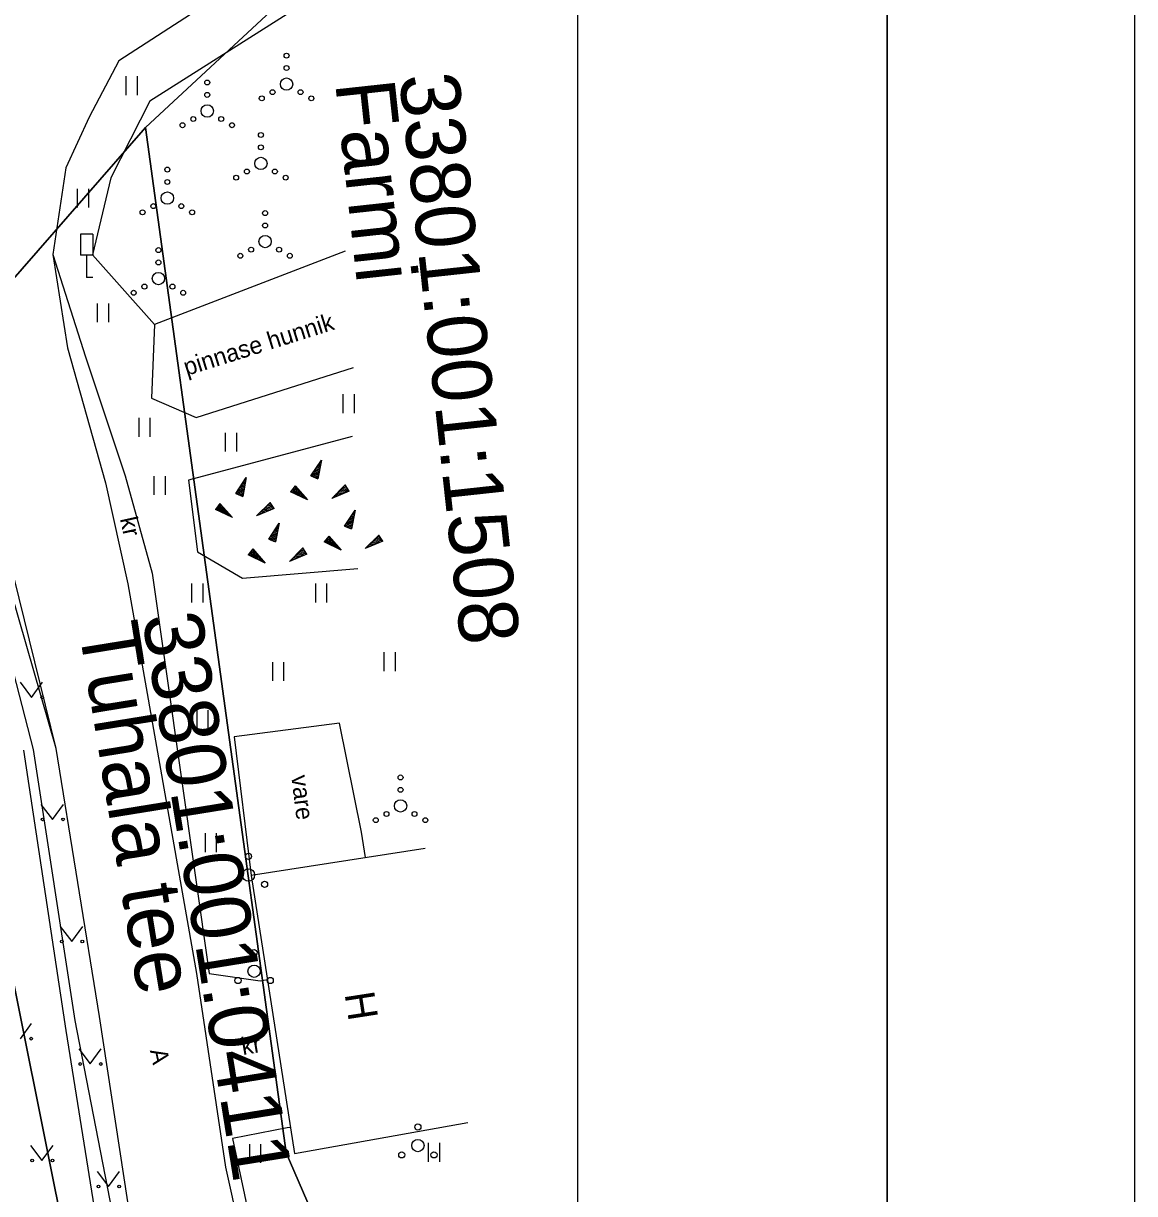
# Model space of a CAD drawing. Extents: x 554947 to 555436, y 6564938 to 6565792.
# Drawn here: x 555348.19 to 555393.07, y 6565480.81 to 6565528.08 of the extents above; entities that cross this region are included whole.
import ezdxf

# ---------------------------------------------------------------- set-up
doc = ezdxf.new("R2010")
doc.units = 0
for name, color, linetype in [('AED', 7, 'Continuous'), ('HALJASTUS', 7, 'Continuous'), ('HOONE', 7, 'Continuous'), ('LIIKLUS', 7, 'Continuous'), ('PIIR', 7, 'Continuous'), ('PR_SIDE', 7, 'Continuous'), ('PUU', 7, 'Continuous'), ('RELJEEF', 7, 'Continuous'), ('TEE', 7, 'Continuous'), ('VORMISTUS_3', 7, 'Continuous')]:
    doc.layers.add(name, color=color, linetype=linetype)

msp = doc.modelspace()

# ---------------------------------------------------------------- linework, layer by layer
at = {"layer": 'AED'}
msp.add_lwpolyline([(555353.187, 6565471.073), (555351.365, 6565478.297), (555349.912, 6565487.399), (555348.203, 6565498.717)], dxfattribs=at)
at = {"layer": 'HALJASTUS'}
for p, q in [((555352.324, 6565525.945), (555352.324, 6565525.183)), ((555352.779, 6565525.945), (555352.779, 6565525.183)), ((555350.36, 6565521.402), (555350.36, 6565520.641)), ((555350.815, 6565521.402), (555350.815, 6565520.641)), ((555351.166, 6565516.766), (555351.166, 6565516.005)), ((555351.621, 6565516.766), (555351.621, 6565516.005)), ((555361.091, 6565513.097), (555361.091, 6565512.335)), ((555361.546, 6565513.097), (555361.546, 6565512.335)), ((555352.843, 6565512.14), (555352.843, 6565511.379)), ((555353.298, 6565512.14), (555353.298, 6565511.379)), ((555356.338, 6565511.545), (555356.338, 6565510.783)), ((555356.793, 6565511.545), (555356.793, 6565510.783)), ((555353.46, 6565509.792), (555353.46, 6565509.031)), ((555353.915, 6565509.792), (555353.915, 6565509.031)), ((555354.98, 6565505.45), (555354.98, 6565504.689)), ((555355.435, 6565505.45), (555355.435, 6565504.689)), ((555359.98, 6565505.45), (555359.98, 6565504.689)), ((555360.435, 6565505.45), (555360.435, 6565504.689)), ((555362.751, 6565502.676), (555362.751, 6565501.915)), ((555363.206, 6565502.676), (555363.206, 6565501.915)), ((555358.242, 6565502.281), (555358.242, 6565501.52)), ((555358.697, 6565502.281), (555358.697, 6565501.52)), ((555348.055, 6565501.461), (555348.518, 6565500.854)), ((555348.518, 6565500.854), (555348.964, 6565501.461)), ((555355.188, 6565500.335), (555355.188, 6565499.574)), ((555355.643, 6565500.335), (555355.643, 6565499.574)), ((555348.895, 6565496.532), (555349.359, 6565495.925)), ((555349.359, 6565495.925), (555349.804, 6565496.532)), ((555355.523, 6565495.364), (555355.523, 6565494.603)), ((555355.978, 6565495.364), (555355.978, 6565494.603)), ((555349.676, 6565491.594), (555350.14, 6565490.987)), ((555350.14, 6565490.987), (555350.585, 6565491.594)), ((555348.068, 6565487.065), (555348.514, 6565487.672)), ((555350.42, 6565486.649), (555350.883, 6565486.043)), ((555350.883, 6565486.043), (555351.329, 6565486.649)), ((555348.474, 6565482.748), (555348.938, 6565482.141)), ((555348.938, 6565482.141), (555349.383, 6565482.748)), ((555357.313, 6565482.807), (555357.313, 6565482.046)), ((555357.768, 6565482.807), (555357.768, 6565482.046)), ((555364.538, 6565482.859), (555364.538, 6565482.097)), ((555364.993, 6565482.859), (555364.993, 6565482.097)), ((555351.163, 6565481.705), (555351.627, 6565481.098)), ((555351.627, 6565481.098), (555352.072, 6565481.705))]:
    msp.add_line(p, q, dxfattribs=at)
for points in [[(555361.377, 6565530.075), (555353.295, 6565524.933), (555351.719, 6565521.845), (555350.973, 6565518.729), (555353.476, 6565515.91)], [(555361.179, 6565518.885), (555353.476, 6565515.91), (555353.355, 6565512.94), (555355.161, 6565512.154), (555361.518, 6565514.185)]]:
    msp.add_lwpolyline(points, dxfattribs=at)
for centre, radius in [((555358.816, 6565526.776), 0.1), ((555358.816, 6565526.276), 0.1), ((555355.614, 6565525.692), 0.1), ((555358.816, 6565525.626), 0.25), ((555355.614, 6565525.192), 0.1), ((555357.816, 6565525.051), 0.1), ((555358.251, 6565525.301), 0.1), ((555359.381, 6565525.301), 0.1), ((555359.816, 6565525.051), 0.1), ((555355.614, 6565524.542), 0.25), ((555355.049, 6565524.217), 0.1), ((555356.179, 6565524.217), 0.1), ((555354.614, 6565523.967), 0.1), ((555356.614, 6565523.967), 0.1), ((555357.781, 6565523.572), 0.1), ((555357.781, 6565523.072), 0.1), ((555357.781, 6565522.422), 0.25), ((555354.001, 6565522.174), 0.1), ((555357.216, 6565522.097), 0.1), ((555358.346, 6565522.097), 0.1), ((555354.001, 6565521.674), 0.1), ((555356.781, 6565521.847), 0.1), ((555358.781, 6565521.847), 0.1), ((555354.001, 6565521.024), 0.25), ((555353.436, 6565520.699), 0.1), ((555354.566, 6565520.699), 0.1), ((555353.001, 6565520.449), 0.1), ((555355.001, 6565520.449), 0.1), ((555357.949, 6565520.416), 0.1), ((555357.949, 6565519.916), 0.1), ((555357.949, 6565519.266), 0.25), ((555353.64, 6565518.922), 0.1), ((555357.384, 6565518.941), 0.1), ((555358.514, 6565518.941), 0.1), ((555353.64, 6565518.422), 0.1), ((555356.949, 6565518.691), 0.1), ((555358.949, 6565518.691), 0.1), ((555353.64, 6565517.772), 0.25), ((555353.075, 6565517.447), 0.1), ((555354.205, 6565517.447), 0.1), ((555352.64, 6565517.197), 0.1), ((555354.64, 6565517.197), 0.1), ((555348.946, 6565500.854), 0.055), ((555363.421, 6565497.618), 0.1), ((555363.421, 6565497.118), 0.1), ((555363.421, 6565496.468), 0.25), ((555362.856, 6565496.143), 0.1), ((555363.986, 6565496.143), 0.1), ((555348.958, 6565495.925), 0.055), ((555349.787, 6565495.925), 0.055), ((555362.421, 6565495.893), 0.1), ((555364.421, 6565495.893), 0.1), ((555349.739, 6565490.987), 0.055), ((555350.567, 6565490.987), 0.055), ((555348.496, 6565487.065), 0.055), ((555350.482, 6565486.043), 0.055), ((555351.311, 6565486.043), 0.055), ((555348.537, 6565482.141), 0.055), ((555349.366, 6565482.141), 0.055), ((555351.225, 6565481.098), 0.055), ((555352.054, 6565481.098), 0.055)]:
    msp.add_circle(centre, radius, dxfattribs=at)
at = {"layer": 'HOONE'}
for points in [[(555361.999, 6565494.379), (555361.839, 6565495.408), (555360.949, 6565499.816), (555356.698, 6565499.263), (555357.386, 6565493.662)], [(555364.41, 6565494.754), (555357.386, 6565493.662), (555359.132, 6565482.428), (555366.132, 6565483.677)]]:
    msp.add_lwpolyline(points, dxfattribs=at)
at = {"layer": 'LIIKLUS'}
for p, q in [((555350.488, 6565519.566), (555350.488, 6565518.716)), ((555350.988, 6565519.566), (555350.488, 6565519.566)), ((555350.988, 6565519.566), (555350.988, 6565518.716)), ((555350.988, 6565518.716), (555350.488, 6565518.716)), ((555350.738, 6565518.716), (555350.738, 6565517.816)), ((555350.988, 6565517.816), (555350.738, 6565517.816))]:
    msp.add_line(p, q, dxfattribs=at)
at = {"layer": 'PIIR'}
for points in [[(555393.069, 6565560.972), (555353.12, 6565523.87), (555343.14, 6565512.46), (555302.6, 6565539.71), (555242.37, 6565583.94), (555179.42, 6565586.32), (555138.98, 6565580.6), (555121.18, 6565602.26), (555116.17, 6565610.5), (555109.96, 6565624.83), (555093.56, 6565628.47), (555079.04, 6565618.4), (555074.13, 6565607.82), (555075.34, 6565593.24), (555091.74, 6565551.94), (555171.91, 6565394.64), (555191.35, 6565341.19), (555195.08, 6565294.61), (555195.28, 6565271.63), (555191.64, 6565237.48)], [(555393.069, 6565456.052), (555368.05, 6565461.11), (555358.8, 6565482.45), (555353.12, 6565523.87), (555393.069, 6565560.972)], [(555393.069, 6565443.872), (555367.06, 6565449.68), (555351.96, 6565468.55), (555343.14, 6565512.46), (555353.12, 6565523.87), (555358.8, 6565482.45), (555368.05, 6565461.11), (555393.069, 6565454.923)]]:
    msp.add_lwpolyline(points, dxfattribs=at)
msp.add_lwpolyline([(555319.44, 6565481.04), (555343.14, 6565512.46), (555351.96, 6565468.55), (555367.06, 6565449.68), (555367.76, 6565374.28), (555361.76, 6565374.07), (555316.84, 6565372.52), (555312.9, 6565433.84), (555323.07, 6565461.26)], close=True, dxfattribs=at)
at = {"layer": 'PR_SIDE'}
msp.add_lwpolyline([(555393.069, 6565447.47), (555392.755, 6565447.532), (555372.326, 6565450.448), (555366.015, 6565452.342), (555363.26, 6565453.626), (555360.292, 6565456.785), (555356.82, 6565461.856), (555353.746, 6565469.93), (555350.28, 6565487.806), (555348.596, 6565498.754), (555346.199, 6565508), (555346.027, 6565508.326), (555343.44, 6565510.968), (555340.158, 6565515.387), (555337.344, 6565518), (555330.24, 6565522.258), (555323.316, 6565526.613), (555319.055, 6565529.304), (555309.687, 6565535.684), (555303.916, 6565540.202)], dxfattribs=at)
at = {"layer": 'PUU'}
for centre, radius in [((555357.278, 6565494.429), 0.125), ((555357.278, 6565493.679), 0.25), ((555356.628, 6565493.304), 0.125), ((555357.928, 6565493.304), 0.125), ((555357.506, 6565490.54), 0.125), ((555357.506, 6565489.79), 0.25), ((555356.856, 6565489.415), 0.125), ((555358.156, 6565489.415), 0.125), ((555364.12, 6565483.497), 0.125), ((555364.12, 6565482.747), 0.25), ((555363.47, 6565482.372), 0.125), ((555364.77, 6565482.372), 0.125)]:
    msp.add_circle(centre, radius, dxfattribs=at)
at = {"layer": 'RELJEEF'}
for p, q in [((555359.803, 6565509.798), (555360.223, 6565510.438)), ((555360.223, 6565510.438), (555360.083, 6565509.683)), ((555360.198, 6565510.398), (555360.218, 6565510.408)), ((555359.803, 6565509.798), (555360.128, 6565509.938)), ((555359.853, 6565509.873), (555360.138, 6565509.993)), ((555359.903, 6565509.948), (555360.153, 6565510.053)), ((555359.953, 6565510.023), (555360.078, 6565510.078)), ((555360.003, 6565510.098), (555360.173, 6565510.173)), ((555360.053, 6565510.173), (555360.183, 6565510.233)), ((555360.078, 6565510.078), (555360.163, 6565510.113)), ((555360.098, 6565510.248), (555360.198, 6565510.288)), ((555360.148, 6565510.323), (555360.208, 6565510.348)), ((555356.77, 6565509.089), (555357.19, 6565509.729)), ((555356.97, 6565509.389), (555357.14, 6565509.464)), ((555357.02, 6565509.464), (555357.15, 6565509.524)), ((555357.19, 6565509.729), (555357.05, 6565508.974)), ((555357.065, 6565509.539), (555357.165, 6565509.579)), ((555357.115, 6565509.614), (555357.175, 6565509.639)), ((555357.165, 6565509.689), (555357.185, 6565509.699)), ((555359.803, 6565509.798), (555360.083, 6565509.683)), ((555359.803, 6565509.798), (555359.803, 6565509.798)), ((555359.868, 6565509.773), (555360.118, 6565509.878)), ((555359.933, 6565509.743), (555360.108, 6565509.818)), ((555360.003, 6565509.718), (555360.098, 6565509.758)), ((555360.068, 6565509.693), (555360.083, 6565509.698)), ((555360.641, 6565508.892), (555361.181, 6565509.437)), ((555361.351, 6565509.187), (555361.181, 6565509.437)), ((555356.77, 6565509.089), (555357.095, 6565509.229)), ((555356.77, 6565509.089), (555357.05, 6565508.974)), ((555356.77, 6565509.089), (555356.77, 6565509.089)), ((555356.82, 6565509.164), (555357.105, 6565509.284)), ((555356.835, 6565509.064), (555357.085, 6565509.169)), ((555356.87, 6565509.239), (555357.12, 6565509.344)), ((555356.9, 6565509.034), (555357.075, 6565509.109)), ((555356.92, 6565509.314), (555357.045, 6565509.369)), ((555356.97, 6565509.009), (555357.065, 6565509.049)), ((555357.035, 6565508.984), (555357.05, 6565508.989)), ((555357.045, 6565509.369), (555357.13, 6565509.404)), ((555359.162, 6565509.397), (555358.977, 6565509.157)), ((555359.667, 6565508.827), (555358.977, 6565509.157)), ((555358.987, 6565509.172), (555358.992, 6565509.152)), ((555359.032, 6565509.227), (555359.047, 6565509.127)), ((555359.077, 6565509.287), (555359.102, 6565509.102)), ((555359.117, 6565509.342), (555359.152, 6565509.072)), ((555359.162, 6565509.397), (555359.667, 6565508.827)), ((555359.162, 6565509.397), (555359.207, 6565509.047)), ((555359.162, 6565509.397), (555359.162, 6565509.397)), ((555359.222, 6565509.332), (555359.262, 6565509.022)), ((555359.282, 6565509.262), (555359.317, 6565508.997)), ((555359.342, 6565509.197), (555359.357, 6565509.057)), ((555359.357, 6565509.057), (555359.372, 6565508.967)), ((555359.397, 6565509.127), (555359.427, 6565508.942)), ((555359.457, 6565509.062), (555359.477, 6565508.917)), ((555359.517, 6565508.992), (555359.532, 6565508.892)), ((555361.351, 6565509.187), (555360.641, 6565508.892)), ((555360.851, 6565508.977), (555360.746, 6565508.997)), ((555360.931, 6565509.012), (555360.791, 6565509.042)), ((555361.016, 6565509.047), (555360.831, 6565509.082)), ((555360.966, 6565509.107), (555360.876, 6565509.127)), ((555361.181, 6565509.117), (555360.916, 6565509.167)), ((555361.266, 6565509.152), (555360.961, 6565509.212)), ((555361.101, 6565509.082), (555360.966, 6565509.107)), ((555361.351, 6565509.187), (555361.001, 6565509.252)), ((555361.311, 6565509.242), (555361.046, 6565509.297)), ((555361.271, 6565509.302), (555361.086, 6565509.337)), ((555361.231, 6565509.362), (555361.131, 6565509.382)), ((555361.191, 6565509.422), (555361.171, 6565509.422)), ((555361.351, 6565509.187), (555361.351, 6565509.187)), ((555356.128, 6565508.688), (555355.943, 6565508.448)), ((555355.998, 6565508.518), (555356.013, 6565508.418)), ((555356.043, 6565508.578), (555356.068, 6565508.393)), ((555356.083, 6565508.633), (555356.118, 6565508.363)), ((555356.128, 6565508.688), (555356.633, 6565508.118)), ((555356.128, 6565508.688), (555356.173, 6565508.338)), ((555356.128, 6565508.688), (555356.128, 6565508.688)), ((555356.188, 6565508.623), (555356.228, 6565508.313)), ((555356.248, 6565508.553), (555356.283, 6565508.288)), ((555356.308, 6565508.488), (555356.323, 6565508.348)), ((555357.608, 6565508.183), (555358.148, 6565508.728)), ((555358.233, 6565508.443), (555357.928, 6565508.503)), ((555358.318, 6565508.478), (555357.968, 6565508.543)), ((555358.278, 6565508.533), (555358.013, 6565508.588)), ((555358.238, 6565508.593), (555358.053, 6565508.628)), ((555358.198, 6565508.653), (555358.098, 6565508.673)), ((555358.158, 6565508.713), (555358.138, 6565508.713)), ((555358.318, 6565508.478), (555358.148, 6565508.728)), ((555359.577, 6565508.927), (555359.587, 6565508.862)), ((555359.637, 6565508.857), (555359.642, 6565508.837)), ((555360.681, 6565508.907), (555360.666, 6565508.912)), ((555360.766, 6565508.942), (555360.706, 6565508.957)), ((555356.633, 6565508.118), (555355.943, 6565508.448)), ((555355.953, 6565508.463), (555355.958, 6565508.443)), ((555356.323, 6565508.348), (555356.338, 6565508.258)), ((555356.363, 6565508.418), (555356.393, 6565508.233)), ((555356.423, 6565508.353), (555356.443, 6565508.208)), ((555356.483, 6565508.283), (555356.498, 6565508.183)), ((555356.543, 6565508.218), (555356.553, 6565508.153)), ((555356.603, 6565508.148), (555356.608, 6565508.128)), ((555358.318, 6565508.478), (555357.608, 6565508.183)), ((555357.648, 6565508.198), (555357.633, 6565508.203)), ((555357.733, 6565508.233), (555357.673, 6565508.248)), ((555357.818, 6565508.268), (555357.713, 6565508.288)), ((555357.898, 6565508.303), (555357.758, 6565508.333)), ((555357.983, 6565508.338), (555357.798, 6565508.373)), ((555357.933, 6565508.398), (555357.843, 6565508.418)), ((555358.148, 6565508.408), (555357.883, 6565508.458)), ((555358.068, 6565508.373), (555357.933, 6565508.398)), ((555358.318, 6565508.478), (555358.318, 6565508.478)), ((555361.161, 6565507.771), (555361.581, 6565508.411)), ((555361.261, 6565507.921), (555361.511, 6565508.026)), ((555361.311, 6565507.996), (555361.436, 6565508.051)), ((555361.361, 6565508.071), (555361.531, 6565508.146)), ((555361.411, 6565508.146), (555361.541, 6565508.206)), ((555361.436, 6565508.051), (555361.521, 6565508.086)), ((555361.581, 6565508.411), (555361.441, 6565507.656)), ((555361.456, 6565508.221), (555361.556, 6565508.261)), ((555361.506, 6565508.296), (555361.566, 6565508.321)), ((555361.556, 6565508.371), (555361.576, 6565508.381)), ((555358.094, 6565507.249), (555358.514, 6565507.889)), ((555358.294, 6565507.549), (555358.464, 6565507.624)), ((555358.344, 6565507.624), (555358.474, 6565507.684)), ((555358.369, 6565507.529), (555358.454, 6565507.564)), ((555358.514, 6565507.889), (555358.374, 6565507.134)), ((555358.389, 6565507.699), (555358.489, 6565507.739)), ((555358.439, 6565507.774), (555358.499, 6565507.799)), ((555358.489, 6565507.849), (555358.509, 6565507.859)), ((555361.161, 6565507.771), (555361.486, 6565507.911)), ((555361.161, 6565507.771), (555361.441, 6565507.656)), ((555361.161, 6565507.771), (555361.161, 6565507.771)), ((555361.211, 6565507.846), (555361.496, 6565507.966)), ((555361.226, 6565507.746), (555361.476, 6565507.851)), ((555361.291, 6565507.716), (555361.466, 6565507.791)), ((555361.361, 6565507.691), (555361.456, 6565507.731)), ((555361.426, 6565507.666), (555361.441, 6565507.671)), ((555358.094, 6565507.249), (555358.419, 6565507.389)), ((555358.094, 6565507.249), (555358.374, 6565507.134)), ((555358.094, 6565507.249), (555358.094, 6565507.249)), ((555358.144, 6565507.324), (555358.429, 6565507.444)), ((555358.159, 6565507.224), (555358.409, 6565507.329)), ((555358.194, 6565507.399), (555358.444, 6565507.504)), ((555358.224, 6565507.194), (555358.399, 6565507.269)), ((555358.244, 6565507.474), (555358.369, 6565507.529)), ((555358.294, 6565507.169), (555358.389, 6565507.209)), ((555358.359, 6565507.144), (555358.374, 6565507.149)), ((555360.519, 6565507.37), (555360.334, 6565507.13)), ((555361.024, 6565506.8), (555360.334, 6565507.13)), ((555360.344, 6565507.145), (555360.349, 6565507.125)), ((555360.389, 6565507.2), (555360.404, 6565507.1)), ((555360.434, 6565507.26), (555360.459, 6565507.075)), ((555360.474, 6565507.315), (555360.509, 6565507.045)), ((555360.519, 6565507.37), (555361.024, 6565506.8)), ((555360.519, 6565507.37), (555360.564, 6565507.02)), ((555360.519, 6565507.37), (555360.519, 6565507.37)), ((555360.579, 6565507.305), (555360.619, 6565506.995)), ((555360.639, 6565507.235), (555360.674, 6565506.97)), ((555360.699, 6565507.17), (555360.714, 6565507.03)), ((555360.754, 6565507.1), (555360.784, 6565506.915)), ((555361.998, 6565506.865), (555362.538, 6565507.41)), ((555362.708, 6565507.16), (555361.998, 6565506.865)), ((555362.323, 6565507.08), (555362.233, 6565507.1)), ((555362.538, 6565507.09), (555362.273, 6565507.14)), ((555362.623, 6565507.125), (555362.318, 6565507.185)), ((555362.458, 6565507.055), (555362.323, 6565507.08)), ((555362.708, 6565507.16), (555362.358, 6565507.225)), ((555362.668, 6565507.215), (555362.403, 6565507.27)), ((555362.628, 6565507.275), (555362.443, 6565507.31)), ((555362.588, 6565507.335), (555362.488, 6565507.355)), ((555362.548, 6565507.395), (555362.528, 6565507.395)), ((555362.708, 6565507.16), (555362.538, 6565507.41)), ((555362.708, 6565507.16), (555362.708, 6565507.16)), ((555357.452, 6565506.849), (555357.267, 6565506.609)), ((555357.957, 6565506.279), (555357.267, 6565506.609)), ((555357.277, 6565506.624), (555357.282, 6565506.604)), ((555357.322, 6565506.679), (555357.337, 6565506.579)), ((555357.367, 6565506.739), (555357.392, 6565506.554)), ((555357.407, 6565506.794), (555357.442, 6565506.524)), ((555357.452, 6565506.849), (555357.957, 6565506.279)), ((555357.452, 6565506.849), (555357.497, 6565506.499)), ((555357.452, 6565506.849), (555357.452, 6565506.849)), ((555357.512, 6565506.784), (555357.552, 6565506.474)), ((555357.572, 6565506.714), (555357.607, 6565506.449)), ((555357.632, 6565506.649), (555357.647, 6565506.509)), ((555358.932, 6565506.344), (555359.472, 6565506.889)), ((555359.642, 6565506.639), (555358.932, 6565506.344)), ((555359.472, 6565506.569), (555359.207, 6565506.619)), ((555359.557, 6565506.604), (555359.252, 6565506.664)), ((555359.642, 6565506.639), (555359.292, 6565506.704)), ((555359.602, 6565506.694), (555359.337, 6565506.749)), ((555359.562, 6565506.754), (555359.377, 6565506.789)), ((555359.522, 6565506.814), (555359.422, 6565506.834)), ((555359.482, 6565506.874), (555359.462, 6565506.874)), ((555359.642, 6565506.639), (555359.472, 6565506.889)), ((555359.642, 6565506.639), (555359.642, 6565506.639)), ((555360.714, 6565507.03), (555360.729, 6565506.94)), ((555360.814, 6565507.035), (555360.834, 6565506.89)), ((555360.874, 6565506.965), (555360.889, 6565506.865)), ((555360.934, 6565506.9), (555360.944, 6565506.835)), ((555360.994, 6565506.83), (555360.999, 6565506.81)), ((555362.038, 6565506.88), (555362.023, 6565506.885)), ((555362.123, 6565506.915), (555362.063, 6565506.93)), ((555362.208, 6565506.95), (555362.103, 6565506.97)), ((555362.288, 6565506.985), (555362.148, 6565507.015)), ((555362.373, 6565507.02), (555362.188, 6565507.055)), ((555357.647, 6565506.509), (555357.662, 6565506.419)), ((555357.687, 6565506.579), (555357.717, 6565506.394)), ((555357.747, 6565506.514), (555357.767, 6565506.369)), ((555357.807, 6565506.444), (555357.822, 6565506.344)), ((555357.867, 6565506.379), (555357.877, 6565506.314)), ((555357.927, 6565506.309), (555357.932, 6565506.289)), ((555358.972, 6565506.359), (555358.957, 6565506.364)), ((555359.057, 6565506.394), (555358.997, 6565506.409)), ((555359.142, 6565506.429), (555359.037, 6565506.449)), ((555359.222, 6565506.464), (555359.082, 6565506.494)), ((555359.307, 6565506.499), (555359.122, 6565506.534)), ((555359.257, 6565506.559), (555359.167, 6565506.579)), ((555359.392, 6565506.534), (555359.257, 6565506.559))]:
    msp.add_line(p, q, dxfattribs=at)
msp.add_lwpolyline([(555361.463, 6565511.386), (555354.86, 6565509.627), (555355.225, 6565506.727), (555357.042, 6565505.67), (555361.69, 6565506.056)], dxfattribs=at)
at = {"layer": 'TEE'}
for points in [[(555360.017, 6565532.032), (555356.722, 6565529.611), (555352.039, 6565526.571), (555350.841, 6565524.289), (555349.902, 6565522.246), (555349.37, 6565518.742), (555349.968, 6565514.969), (555351.498, 6565509.514), (555352.399, 6565505.44), (555355.185, 6565489.693), (555356.356, 6565481.874), (555358.536, 6565472.027), (555360.203, 6565467.288), (555362.127, 6565463.387), (555364.998, 6565459.532), (555367.923, 6565457.754), (555371.76, 6565456.513), (555378.11, 6565454.853), (555393.069, 6565452.684)], [(555393.069, 6565448.493), (555392.904, 6565448.521), (555377.792, 6565450.52), (555372.547, 6565451.424), (555369.187, 6565452.37), (555366.443, 6565453.255), (555364.23, 6565454.662), (555361.13, 6565458.083), (555357.411, 6565463.749), (555354.693, 6565470.258), (555353.748, 6565473.64), (555352.733, 6565478.362), (555351.267, 6565487.961), (555349.516, 6565498.784), (555347.141, 6565508.358), (555345.332, 6565511.802), (555341.773, 6565516.752), (555338.53, 6565519.62), (555330.669, 6565524.333), (555325.029, 6565527.171), (555324.447, 6565527.997), (555320.204, 6565530.941)], [(555349.516, 6565498.784), (555346.789, 6565508.206), (555344.895, 6565511.389), (555341.304, 6565516.362), (555338.53, 6565519.62)], [(555349.37, 6565518.742), (555350.702, 6565514.609), (555352.294, 6565509.808), (555353.389, 6565505.873), (555355.685, 6565489.704), (555357.745, 6565489.405), (555358.04, 6565489.451)], [(555358.969, 6565483.478), (555358.843, 6565483.458), (555356.63, 6565483.037), (555358.965, 6565472.102), (555360.762, 6565467.568), (555362.536, 6565463.692), (555365.5, 6565460.084), (555367.923, 6565457.754)]]:
    msp.add_lwpolyline(points, dxfattribs=at)
at = {"layer": 'VORMISTUS_3'}
for points in [[(555183.069, 6565701.752), (555393.069, 6565701.752), (555393.069, 6565404.752), (555183.069, 6565404.752)], [(555193.069, 6565415.752), (555383.069, 6565415.752), (555383.069, 6565690.752), (555193.069, 6565690.752)], [(555193.069, 6565690.752), (555383.069, 6565690.752), (555383.069, 6565415.752), (555193.069, 6565415.752)], [(555370.569, 6565441.752), (555205.569, 6565441.752), (555205.569, 6565651.752), (555370.569, 6565651.752)]]:
    msp.add_lwpolyline(points, close=True, dxfattribs=at)

# ---------------------------------------------------------------- texts
at = {"layer": 'HALJASTUS'}
msp.add_text('pinnase hunnik', height=0.7, rotation=17.4286, dxfattribs=at).set_placement((555354.784, 6565513.837))
at = {"layer": 'HOONE'}
for s, height, rotation, p in [('vare', 0.7, 277.0041, (555359.004, 6565497.676)), ('H', 1.2, 278.8351, (555361.157, 6565488.875))]:
    msp.add_text(s, height=height, rotation=rotation, dxfattribs=at).set_placement(p)
at = {"layer": 'PIIR'}
for s, rotation, p in [('33801:001:1508', 276.1984, (555363.362, 6565525.96)), ('Farmi', 276.1984, (555360.777, 6565525.679)), ('33801:001:0411', 279.2075, (555352.979, 6565504.107)), ('Tuhala tee', 279.2075, (555350.412, 6565503.691))]:
    msp.add_text(s, height=2.4, rotation=rotation, dxfattribs=at).set_placement(p)
at = {"layer": 'TEE'}
for s, rotation, p in [('kr', 282.4255, (555352.084, 6565508.068)), ('kr', 9.7665, (555357.052, 6565486.401)), ('A', 282.0011, (555353.293, 6565486.59))]:
    msp.add_text(s, height=0.7, rotation=rotation, dxfattribs=at).set_placement(p)

doc.saveas('drawing.dxf')
